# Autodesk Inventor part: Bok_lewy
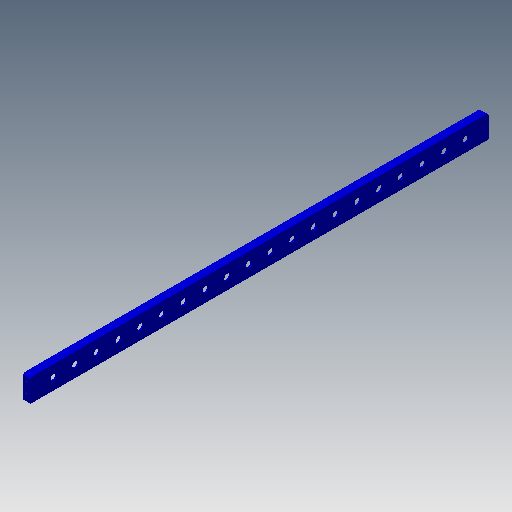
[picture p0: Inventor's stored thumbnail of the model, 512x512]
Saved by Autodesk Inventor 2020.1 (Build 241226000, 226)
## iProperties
Created: 2005-09
Part Number: Bok_lewy
Document SubType Name: Modeling
Description: Bok przenośnika - lewy
Density: 1 g/cm^3
Material: Ogólny
Appearance: Niebieski
Designer: F.Stasiak
Manager: www.cadconsulting.pl
Company: Fabian Stasiak CAD Consulting
Author: F.Stasiak
Subject: Zbiór ćwiczeń. Autodesk Inventor 2020. Kurs podstawowy
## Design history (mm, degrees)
node "Bok_prawy" dims "d0" = 10
node "Otwory3"
node "Otwory5"
node "Bryła1"
node "Korpusy bryłowe"
node "Korpusy powierzchniowe"
tag "Bryła wyprowadzona2"
feature "Bryła1::Bok_prawy" dims "d0" = 10
sketch "Szkic3"
  geometry: 1 further point
hole "Hole3" sketch "Szkic3" diameter "d15" = 6.647; stored, may be unused: countersink angle "d19" = 90 deg, drill point angle "d21" = 120 deg; dims "d16" = 18.9, "d17" = 4, "d18" = 2, "d20" = 22.9
sketch "Szkic5"
  geometry: 1 further point
hole "Hole5" sketch "Szkic5" diameter "d29" = 6.647; stored, may be unused: countersink angle "d33" = 90 deg, drill point angle "d35" = 120 deg; dims "d30" = 18.9, "d31" = 4, "d32" = 2, "d34" = 22.9
